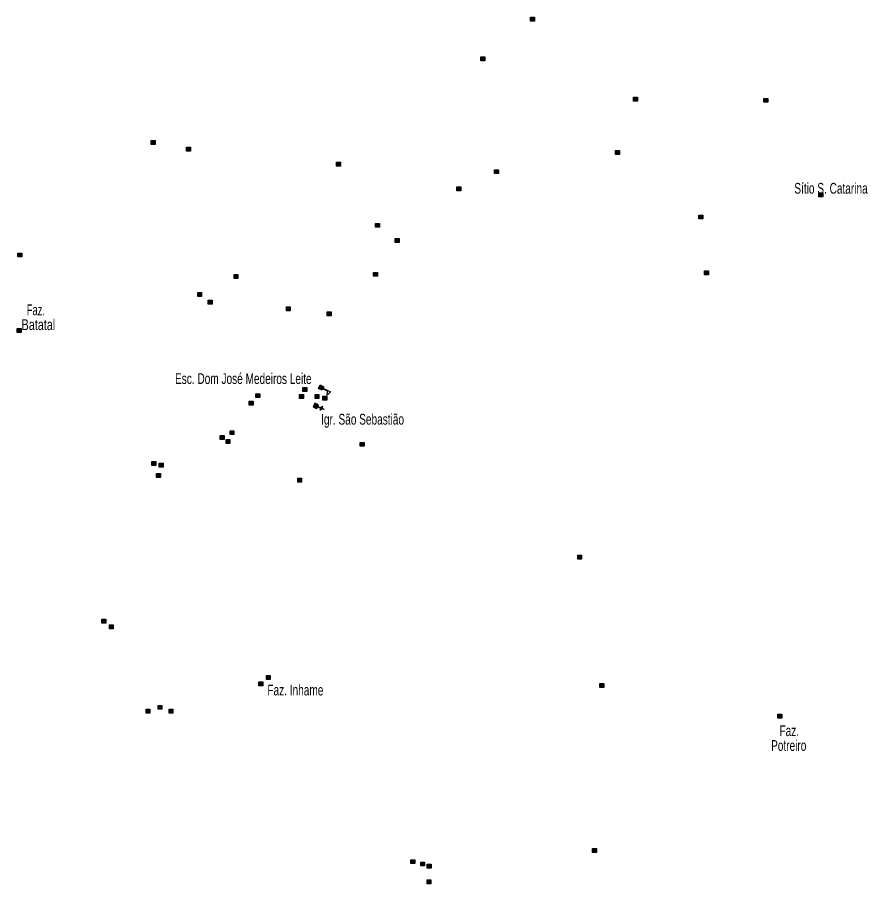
# Model space of a CAD drawing. Extents: x 447.8 to 473.9, y 7733.1 to 7760.8.
# Drawn here: x 467.58 to 473.9, y 7740.03 to 7746.47 of the extents above; entities that cross this region are included whole.
import ezdxf
from ezdxf.enums import TextEntityAlignment as Align

# ---------------------------------------------------------------- set-up
doc = ezdxf.new("R2010")
doc.units = 0
doc.header["$LTSCALE"] = 0.032
for name, color, linetype, lineweight in [('2', 7, 'Continuous', 25), ('4', 7, 'Continuous', 25), ('6', 7, 'Continuous', 25)]:
    doc.layers.add(name, color=color, linetype=linetype, lineweight=lineweight)
doc.layers.add('61', color=7, linetype='Continuous')

msp = doc.modelspace()

# ---------------------------------------------------------------- hatches: boundary and pattern name
at = {"layer": '2'}
for points in [[(471.3938, 7746.4717), (471.4228, 7746.4717), (471.4228, 7746.4427), (471.3938, 7746.4427)], [(471.0253, 7746.1778), (471.0543, 7746.1778), (471.0543, 7746.1488), (471.0253, 7746.1488)], [(472.1606, 7745.8774), (472.1896, 7745.8774), (472.1896, 7745.8484), (472.1606, 7745.8484)], [(473.1297, 7745.8689), (473.1587, 7745.8689), (473.1587, 7745.8399), (473.1297, 7745.8399)], [(468.5743, 7745.555), (468.6033, 7745.555), (468.6033, 7745.526), (468.5743, 7745.526)], [(468.8375, 7745.5069), (468.8665, 7745.5069), (468.8665, 7745.4779), (468.8375, 7745.4779)], [(472.0264, 7745.4813), (472.0554, 7745.4813), (472.0554, 7745.4523), (472.0264, 7745.4523)], [(469.9522, 7745.3948), (469.9812, 7745.3948), (469.9812, 7745.3658), (469.9522, 7745.3658)], [(471.1276, 7745.3386), (471.1566, 7745.3386), (471.1566, 7745.3096), (471.1276, 7745.3096)], [(470.8464, 7745.2108), (470.8754, 7745.2108), (470.8754, 7745.1818), (470.8464, 7745.1818)], [(473.5387, 7745.166), (473.5677, 7745.166), (473.5677, 7745.137), (473.5387, 7745.137)], [(472.6462, 7745.002), (472.6752, 7745.002), (472.6752, 7744.973), (472.6462, 7744.973)], [(470.2415, 7744.9403), (470.2705, 7744.9403), (470.2705, 7744.9113), (470.2415, 7744.9113)], [(470.3885, 7744.8274), (470.4175, 7744.8274), (470.4175, 7744.7984), (470.3885, 7744.7984)], [(467.5832, 7744.7196), (467.6122, 7744.7196), (467.6122, 7744.6906), (467.5832, 7744.6906)], [(469.19, 7744.5593), (469.219, 7744.5593), (469.219, 7744.5303), (469.19, 7744.5303)], [(470.2266, 7744.576), (470.2556, 7744.576), (470.2556, 7744.547), (470.2266, 7744.547)], [(472.6888, 7744.5867), (472.7178, 7744.5867), (472.7178, 7744.5577), (472.6888, 7744.5577)], [(468.9199, 7744.4266), (468.9489, 7744.4266), (468.9489, 7744.3976), (468.9199, 7744.3976)], [(468.9977, 7744.3694), (469.0267, 7744.3694), (469.0267, 7744.3404), (468.9977, 7744.3404)], [(469.5791, 7744.319), (469.6081, 7744.319), (469.6081, 7744.29), (469.5791, 7744.29)], [(469.8835, 7744.2824), (469.9125, 7744.2824), (469.9125, 7744.2534), (469.8835, 7744.2534)], [(467.5786, 7744.1588), (467.6076, 7744.1588), (467.6076, 7744.1298), (467.5786, 7744.1298)], [(469.7027, 7743.7193), (469.7317, 7743.7193), (469.7317, 7743.6903), (469.7027, 7743.6903)], [(469.3525, 7743.6736), (469.3815, 7743.6736), (469.3815, 7743.6446), (469.3525, 7743.6446)], [(469.6775, 7743.6667), (469.7065, 7743.6667), (469.7065, 7743.6377), (469.6775, 7743.6377)], [(469.792, 7743.6667), (469.821, 7743.6667), (469.821, 7743.6377), (469.792, 7743.6377)], [(469.8499, 7743.6544), (469.8789, 7743.6544), (469.8789, 7743.6254), (469.8499, 7743.6254)], [(469.3021, 7743.6186), (469.3311, 7743.6186), (469.3311, 7743.5896), (469.3021, 7743.5896)], [(469.1602, 7743.3989), (469.1892, 7743.3989), (469.1892, 7743.3699), (469.1602, 7743.3699)], [(469.087, 7743.3623), (469.116, 7743.3623), (469.116, 7743.3333), (469.087, 7743.3333)], [(469.1305, 7743.3325), (469.1595, 7743.3325), (469.1595, 7743.3035), (469.1305, 7743.3035)], [(470.1284, 7743.3119), (470.1574, 7743.3119), (470.1574, 7743.2829), (470.1284, 7743.2829)], [(468.5789, 7743.17), (468.6079, 7743.17), (468.6079, 7743.141), (468.5789, 7743.141)], [(468.6338, 7743.1563), (468.6628, 7743.1563), (468.6628, 7743.1273), (468.6338, 7743.1273)], [(468.6132, 7743.0807), (468.6422, 7743.0807), (468.6422, 7743.0517), (468.6132, 7743.0517)], [(469.6638, 7743.0464), (469.6928, 7743.0464), (469.6928, 7743.0174), (469.6638, 7743.0174)], [(471.7453, 7742.4738), (471.7743, 7742.4738), (471.7743, 7742.4448), (471.7453, 7742.4448)], [(468.2081, 7741.9981), (468.2371, 7741.9981), (468.2371, 7741.9691), (468.2081, 7741.9691)], [(468.263, 7741.9546), (468.292, 7741.9546), (468.292, 7741.9256), (468.263, 7741.9256)], [(469.4303, 7741.5793), (469.4593, 7741.5793), (469.4593, 7741.5503), (469.4303, 7741.5503)], [(469.3754, 7741.5312), (469.4044, 7741.5312), (469.4044, 7741.5022), (469.3754, 7741.5022)], [(471.9093, 7741.5195), (471.9383, 7741.5195), (471.9383, 7741.4905), (471.9093, 7741.4905)], [(468.5354, 7741.3275), (468.5644, 7741.3275), (468.5644, 7741.2985), (468.5354, 7741.2985)], [(468.6246, 7741.3572), (468.6536, 7741.3572), (468.6536, 7741.3282), (468.6246, 7741.3282)], [(468.707, 7741.3275), (468.736, 7741.3275), (468.736, 7741.2985), (468.707, 7741.2985)], [(473.2341, 7741.2916), (473.2631, 7741.2916), (473.2631, 7741.2626), (473.2341, 7741.2626)], [(471.856, 7740.2927), (471.885, 7740.2927), (471.885, 7740.2637), (471.856, 7740.2637)], [(470.5056, 7740.2096), (470.5346, 7740.2096), (470.5346, 7740.1806), (470.5056, 7740.1806)], [(470.5781, 7740.1926), (470.6071, 7740.1926), (470.6071, 7740.1636), (470.5781, 7740.1636)], [(470.627, 7740.1755), (470.656, 7740.1755), (470.656, 7740.1465), (470.627, 7740.1465)], [(470.6249, 7740.0605), (470.6539, 7740.0605), (470.6539, 7740.0315), (470.6249, 7740.0315)]]:
    msp.add_hatch(color=256, dxfattribs=at).paths.add_polyline_path(points)
at = {"layer": '4'}
msp.add_hatch(color=256, dxfattribs=at).paths.add_polyline_path([(469.8301, 7743.7389), (469.8572, 7743.7261), (469.8444, 7743.6989), (469.8173, 7743.7118)])
at = {"layer": '6'}
for points in [[(469.8175, 7743.5908), (469.7898, 7743.6023), (469.7782, 7743.5746), (469.8059, 7743.5631)], [(469.8107, 7743.5746), (469.8127, 7743.5792), (469.8381, 7743.5687), (469.8429, 7743.5802), (469.8475, 7743.5783), (469.8427, 7743.5668), (469.8588, 7743.56), (469.8569, 7743.5554), (469.8408, 7743.5621), (469.8359, 7743.5506), (469.8313, 7743.5525), (469.8361, 7743.5641)]]:
    msp.add_hatch(color=256, dxfattribs=at).paths.add_polyline_path(points)

# ---------------------------------------------------------------- linework, layer by layer
at = {"layer": '2'}
for points in [[(471.3938, 7746.4717), (471.4228, 7746.4717), (471.4228, 7746.4427), (471.3938, 7746.4427)], [(471.0253, 7746.1778), (471.0543, 7746.1778), (471.0543, 7746.1488), (471.0253, 7746.1488)], [(472.1606, 7745.8774), (472.1896, 7745.8774), (472.1896, 7745.8484), (472.1606, 7745.8484)], [(473.1297, 7745.8689), (473.1587, 7745.8689), (473.1587, 7745.8399), (473.1297, 7745.8399)], [(468.5743, 7745.555), (468.6033, 7745.555), (468.6033, 7745.526), (468.5743, 7745.526)], [(468.8375, 7745.5069), (468.8665, 7745.5069), (468.8665, 7745.4779), (468.8375, 7745.4779)], [(472.0264, 7745.4813), (472.0554, 7745.4813), (472.0554, 7745.4523), (472.0264, 7745.4523)], [(469.9522, 7745.3948), (469.9812, 7745.3948), (469.9812, 7745.3658), (469.9522, 7745.3658)], [(471.1276, 7745.3386), (471.1566, 7745.3386), (471.1566, 7745.3096), (471.1276, 7745.3096)], [(470.8464, 7745.2108), (470.8754, 7745.2108), (470.8754, 7745.1818), (470.8464, 7745.1818)], [(473.5387, 7745.166), (473.5677, 7745.166), (473.5677, 7745.137), (473.5387, 7745.137)], [(472.6462, 7745.002), (472.6752, 7745.002), (472.6752, 7744.973), (472.6462, 7744.973)], [(470.2415, 7744.9403), (470.2705, 7744.9403), (470.2705, 7744.9113), (470.2415, 7744.9113)], [(470.3885, 7744.8274), (470.4175, 7744.8274), (470.4175, 7744.7984), (470.3885, 7744.7984)], [(467.5832, 7744.7196), (467.6122, 7744.7196), (467.6122, 7744.6906), (467.5832, 7744.6906)], [(469.19, 7744.5593), (469.219, 7744.5593), (469.219, 7744.5303), (469.19, 7744.5303)], [(470.2266, 7744.576), (470.2556, 7744.576), (470.2556, 7744.547), (470.2266, 7744.547)], [(472.6888, 7744.5867), (472.7178, 7744.5867), (472.7178, 7744.5577), (472.6888, 7744.5577)], [(468.9199, 7744.4266), (468.9489, 7744.4266), (468.9489, 7744.3976), (468.9199, 7744.3976)], [(468.9977, 7744.3694), (469.0267, 7744.3694), (469.0267, 7744.3404), (468.9977, 7744.3404)], [(469.5791, 7744.319), (469.6081, 7744.319), (469.6081, 7744.29), (469.5791, 7744.29)], [(469.8835, 7744.2824), (469.9125, 7744.2824), (469.9125, 7744.2534), (469.8835, 7744.2534)], [(467.5786, 7744.1588), (467.6076, 7744.1588), (467.6076, 7744.1298), (467.5786, 7744.1298)], [(469.7027, 7743.7193), (469.7317, 7743.7193), (469.7317, 7743.6903), (469.7027, 7743.6903)], [(469.3525, 7743.6736), (469.3815, 7743.6736), (469.3815, 7743.6446), (469.3525, 7743.6446)], [(469.6775, 7743.6667), (469.7065, 7743.6667), (469.7065, 7743.6377), (469.6775, 7743.6377)], [(469.792, 7743.6667), (469.821, 7743.6667), (469.821, 7743.6377), (469.792, 7743.6377)], [(469.8499, 7743.6544), (469.8789, 7743.6544), (469.8789, 7743.6254), (469.8499, 7743.6254)], [(469.3021, 7743.6186), (469.3311, 7743.6186), (469.3311, 7743.5896), (469.3021, 7743.5896)], [(469.1602, 7743.3989), (469.1892, 7743.3989), (469.1892, 7743.3699), (469.1602, 7743.3699)], [(469.087, 7743.3623), (469.116, 7743.3623), (469.116, 7743.3333), (469.087, 7743.3333)], [(469.1305, 7743.3325), (469.1595, 7743.3325), (469.1595, 7743.3035), (469.1305, 7743.3035)], [(470.1284, 7743.3119), (470.1574, 7743.3119), (470.1574, 7743.2829), (470.1284, 7743.2829)], [(468.5789, 7743.17), (468.6079, 7743.17), (468.6079, 7743.141), (468.5789, 7743.141)], [(468.6338, 7743.1563), (468.6628, 7743.1563), (468.6628, 7743.1273), (468.6338, 7743.1273)], [(468.6132, 7743.0807), (468.6422, 7743.0807), (468.6422, 7743.0517), (468.6132, 7743.0517)], [(469.6638, 7743.0464), (469.6928, 7743.0464), (469.6928, 7743.0174), (469.6638, 7743.0174)], [(471.7453, 7742.4738), (471.7743, 7742.4738), (471.7743, 7742.4448), (471.7453, 7742.4448)], [(468.2081, 7741.9981), (468.2371, 7741.9981), (468.2371, 7741.9691), (468.2081, 7741.9691)], [(468.263, 7741.9546), (468.292, 7741.9546), (468.292, 7741.9256), (468.263, 7741.9256)], [(469.4303, 7741.5793), (469.4593, 7741.5793), (469.4593, 7741.5503), (469.4303, 7741.5503)], [(469.3754, 7741.5312), (469.4044, 7741.5312), (469.4044, 7741.5022), (469.3754, 7741.5022)], [(471.9093, 7741.5195), (471.9383, 7741.5195), (471.9383, 7741.4905), (471.9093, 7741.4905)], [(468.5354, 7741.3275), (468.5644, 7741.3275), (468.5644, 7741.2985), (468.5354, 7741.2985)], [(468.6246, 7741.3572), (468.6536, 7741.3572), (468.6536, 7741.3282), (468.6246, 7741.3282)], [(468.707, 7741.3275), (468.736, 7741.3275), (468.736, 7741.2985), (468.707, 7741.2985)], [(473.2341, 7741.2916), (473.2631, 7741.2916), (473.2631, 7741.2626), (473.2341, 7741.2626)], [(471.856, 7740.2927), (471.885, 7740.2927), (471.885, 7740.2637), (471.856, 7740.2637)], [(470.5056, 7740.2096), (470.5346, 7740.2096), (470.5346, 7740.1806), (470.5056, 7740.1806)], [(470.5781, 7740.1926), (470.6071, 7740.1926), (470.6071, 7740.1636), (470.5781, 7740.1636)], [(470.627, 7740.1755), (470.656, 7740.1755), (470.656, 7740.1465), (470.627, 7740.1465)], [(470.6249, 7740.0605), (470.6539, 7740.0605), (470.6539, 7740.0315), (470.6249, 7740.0315)]]:
    msp.add_lwpolyline(points, close=True, dxfattribs=at)
at = {"layer": '4'}
msp.add_line((469.8519, 7743.7148), (469.8497, 7743.7103), dxfattribs=at)
for points in [[(469.8301, 7743.7389), (469.8572, 7743.7261), (469.8444, 7743.6989), (469.8173, 7743.7118)], [(469.8519, 7743.7148), (469.9084, 7743.6881), (469.8821, 7743.6618), (469.8855, 7743.6934), (469.8497, 7743.7103)]]:
    msp.add_lwpolyline(points, close=True, dxfattribs=at)
at = {"layer": '6'}
for points in [[(469.8175, 7743.5908), (469.7898, 7743.6023), (469.7782, 7743.5746), (469.8059, 7743.5631)], [(469.8107, 7743.5746), (469.8127, 7743.5792), (469.8381, 7743.5687), (469.8429, 7743.5802), (469.8475, 7743.5783), (469.8427, 7743.5668), (469.8588, 7743.56), (469.8569, 7743.5554), (469.8408, 7743.5621), (469.8359, 7743.5506), (469.8313, 7743.5525), (469.8361, 7743.5641)]]:
    msp.add_lwpolyline(points, close=True, dxfattribs=at)

# ---------------------------------------------------------------- texts
at = {"layer": '61', "width": 0.7}
for s, p in [('Sítio S. Catarina', (473.9013, 7745.1608)), ('Esc. Dom José Medeiros Leite', (469.7668, 7743.746))]:
    msp.add_text(s, height=0.08, dxfattribs=at).set_placement(p, align=Align.RIGHT)
at = {"layer": '61'}
for s, width, p in [('  Faz.', 0.65, (467.6103, 7744.257)), ('Batatal ', 0.75, (467.6103, 7744.147)), ('Igr. São Sebastião', 0.7, (469.8376, 7743.444)), ('Faz. Inhame', 0.7, (469.4379, 7741.431)), ('   Faz.', 0.7, (473.1832, 7741.1286)), ('Potreiro', 0.7, (473.1832, 7741.0186))]:
    msp.add_text(s, height=0.08, dxfattribs=dict(at, width=width)).set_placement(p)

doc.saveas('drawing.dxf')
